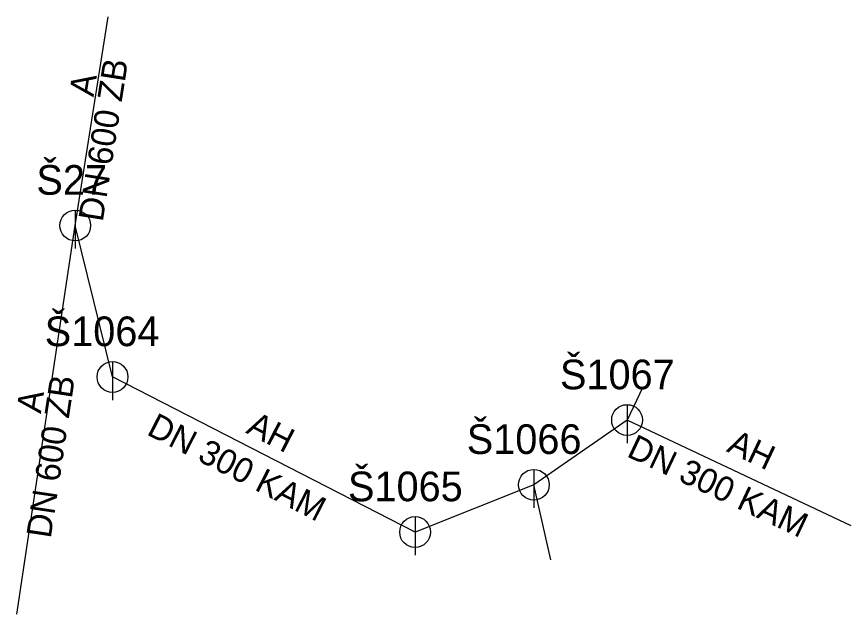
# Model space of a CAD drawing. Extents: x -482685.1 to -482630.9, y -1126638.6 to -1126599.8.
import ezdxf

# ---------------------------------------------------------------- set-up
doc = ezdxf.new("R2010")
doc.units = 0
for name, color, linetype in [('_pripojka_kanal_destova_priblizne_', 7, 'Continuous'), ('_pripojka_kanal_jednotna_priblizne_', 7, 'Continuous'), ('_stoka_jednotna_smvak_prevzato_z_dokumentace_', 7, 'Continuous'), ('_stoka_jednotna_smvak_priblizne_', 7, 'Continuous'), ('Default', 7, 'Continuous'), ('MoLevel 1', 7, 'Continuous'), ('MoLevel 119', 7, 'Continuous'), ('MoLevel 120', 7, 'Continuous'), ('MoLevel 2', 7, 'Continuous'), ('MoLevel 68', 7, 'Continuous'), ('MoLevel 69', 7, 'Continuous')]:
    doc.layers.add(name, color=color, linetype=linetype)

# ---------------------------------------------------------------- blocks, each defined once
blk = doc.blocks.new('_sachta_kanal_prevzato_z_dokumentace_')
at = {"layer": 'Default'}
blk.add_line((0, 0.00005), (0, -0.000075), dxfattribs=at)
blk.add_circle((0, 0), 0.00005, dxfattribs=at)

msp = doc.modelspace()

# ---------------------------------------------------------------- linework, layer by layer
at = {"layer": '_pripojka_kanal_destova_priblizne_'}
msp.add_line((-482650.447, -1126635.043), (-482651.55, -1126630.17), dxfattribs=at)
at = {"layer": '_pripojka_kanal_jednotna_priblizne_'}
msp.add_line((-482644.509, -1126623.871), (-482645.5, -1126625.97), dxfattribs=at)
at = {"layer": '_stoka_jednotna_smvak_prevzato_z_dokumentace_'}
for p, q in [((-482681.32, -1126613.34), (-482679.18, -1126599.78)), ((-482685.12, -1126638.58), (-482681.32, -1126613.34)), ((-482678.9, -1126623.17), (-482681.32, -1126613.34)), ((-482659.26, -1126633.24), (-482678.9, -1126623.17)), ((-482645.5, -1126625.97), (-482651.55, -1126630.17)), ((-482651.55, -1126630.17), (-482659.26, -1126633.24))]:
    msp.add_line(p, q, dxfattribs=at)
at = {"layer": '_stoka_jednotna_smvak_priblizne_'}
msp.add_line((-482630.946, -1126632.826), (-482645.5, -1126625.97), dxfattribs=at)

# ---------------------------------------------------------------- block references
at = {"layer": 'MoLevel 119', "xscale": 20000, "yscale": 20000}
for p in [(-482681.32, -1126613.34), (-482678.9, -1126623.17), (-482645.5, -1126625.97), (-482651.55, -1126630.17), (-482659.26, -1126633.24)]:
    msp.add_blockref('_sachta_kanal_prevzato_z_dokumentace_', p, dxfattribs=at)

# ---------------------------------------------------------------- texts
at = {"layer": 'MoLevel 1'}
msp.add_text('DN 300 KAM', height=1.6049, rotation=334.7772, dxfattribs=at).set_placement((-482645.593, -1126628.3))
at = {"layer": 'MoLevel 120'}
for s, p in [('Š27', (-482683.842, -1126611.34)), ('Š1064', (-482683.302, -1126621.17)), ('Š1067', (-482649.856, -1126623.97)), ('Š1066', (-482655.906, -1126628.17)), ('Š1065', (-482663.616, -1126631.24))]:
    msp.add_text(s, height=1.9259, dxfattribs=at).set_placement(p)
at = {"layer": 'MoLevel 2'}
msp.add_text('AH', height=1.6049, rotation=334.7772, dxfattribs=at).set_placement((-482639.102, -1126627.984))
at = {"layer": 'MoLevel 68'}
for s, rotation, p in [('DN 600 ZB', 81.0317, (-482679.537, -1126613.139)), ('DN 600 ZB', 81.4382, (-482682.913, -1126633.691)), ('DN 300 KAM', 332.8545, (-482676.749, -1126626.876))]:
    msp.add_text(s, height=1.6049, rotation=rotation, dxfattribs=at).set_placement(p)
at = {"layer": 'MoLevel 69'}
for s, height, rotation, p in [('A', 1.605, 81.0317, (-482680.134, -1126605.023)), ('A', 1.605, 81.4382, (-482683.555, -1126625.58)), ('AH', 1.6049, 332.8545, (-482670.304, -1126626.777))]:
    msp.add_text(s, height=height, rotation=rotation, dxfattribs=at).set_placement(p)

doc.saveas('drawing.dxf')
